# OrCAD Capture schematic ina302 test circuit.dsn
size C
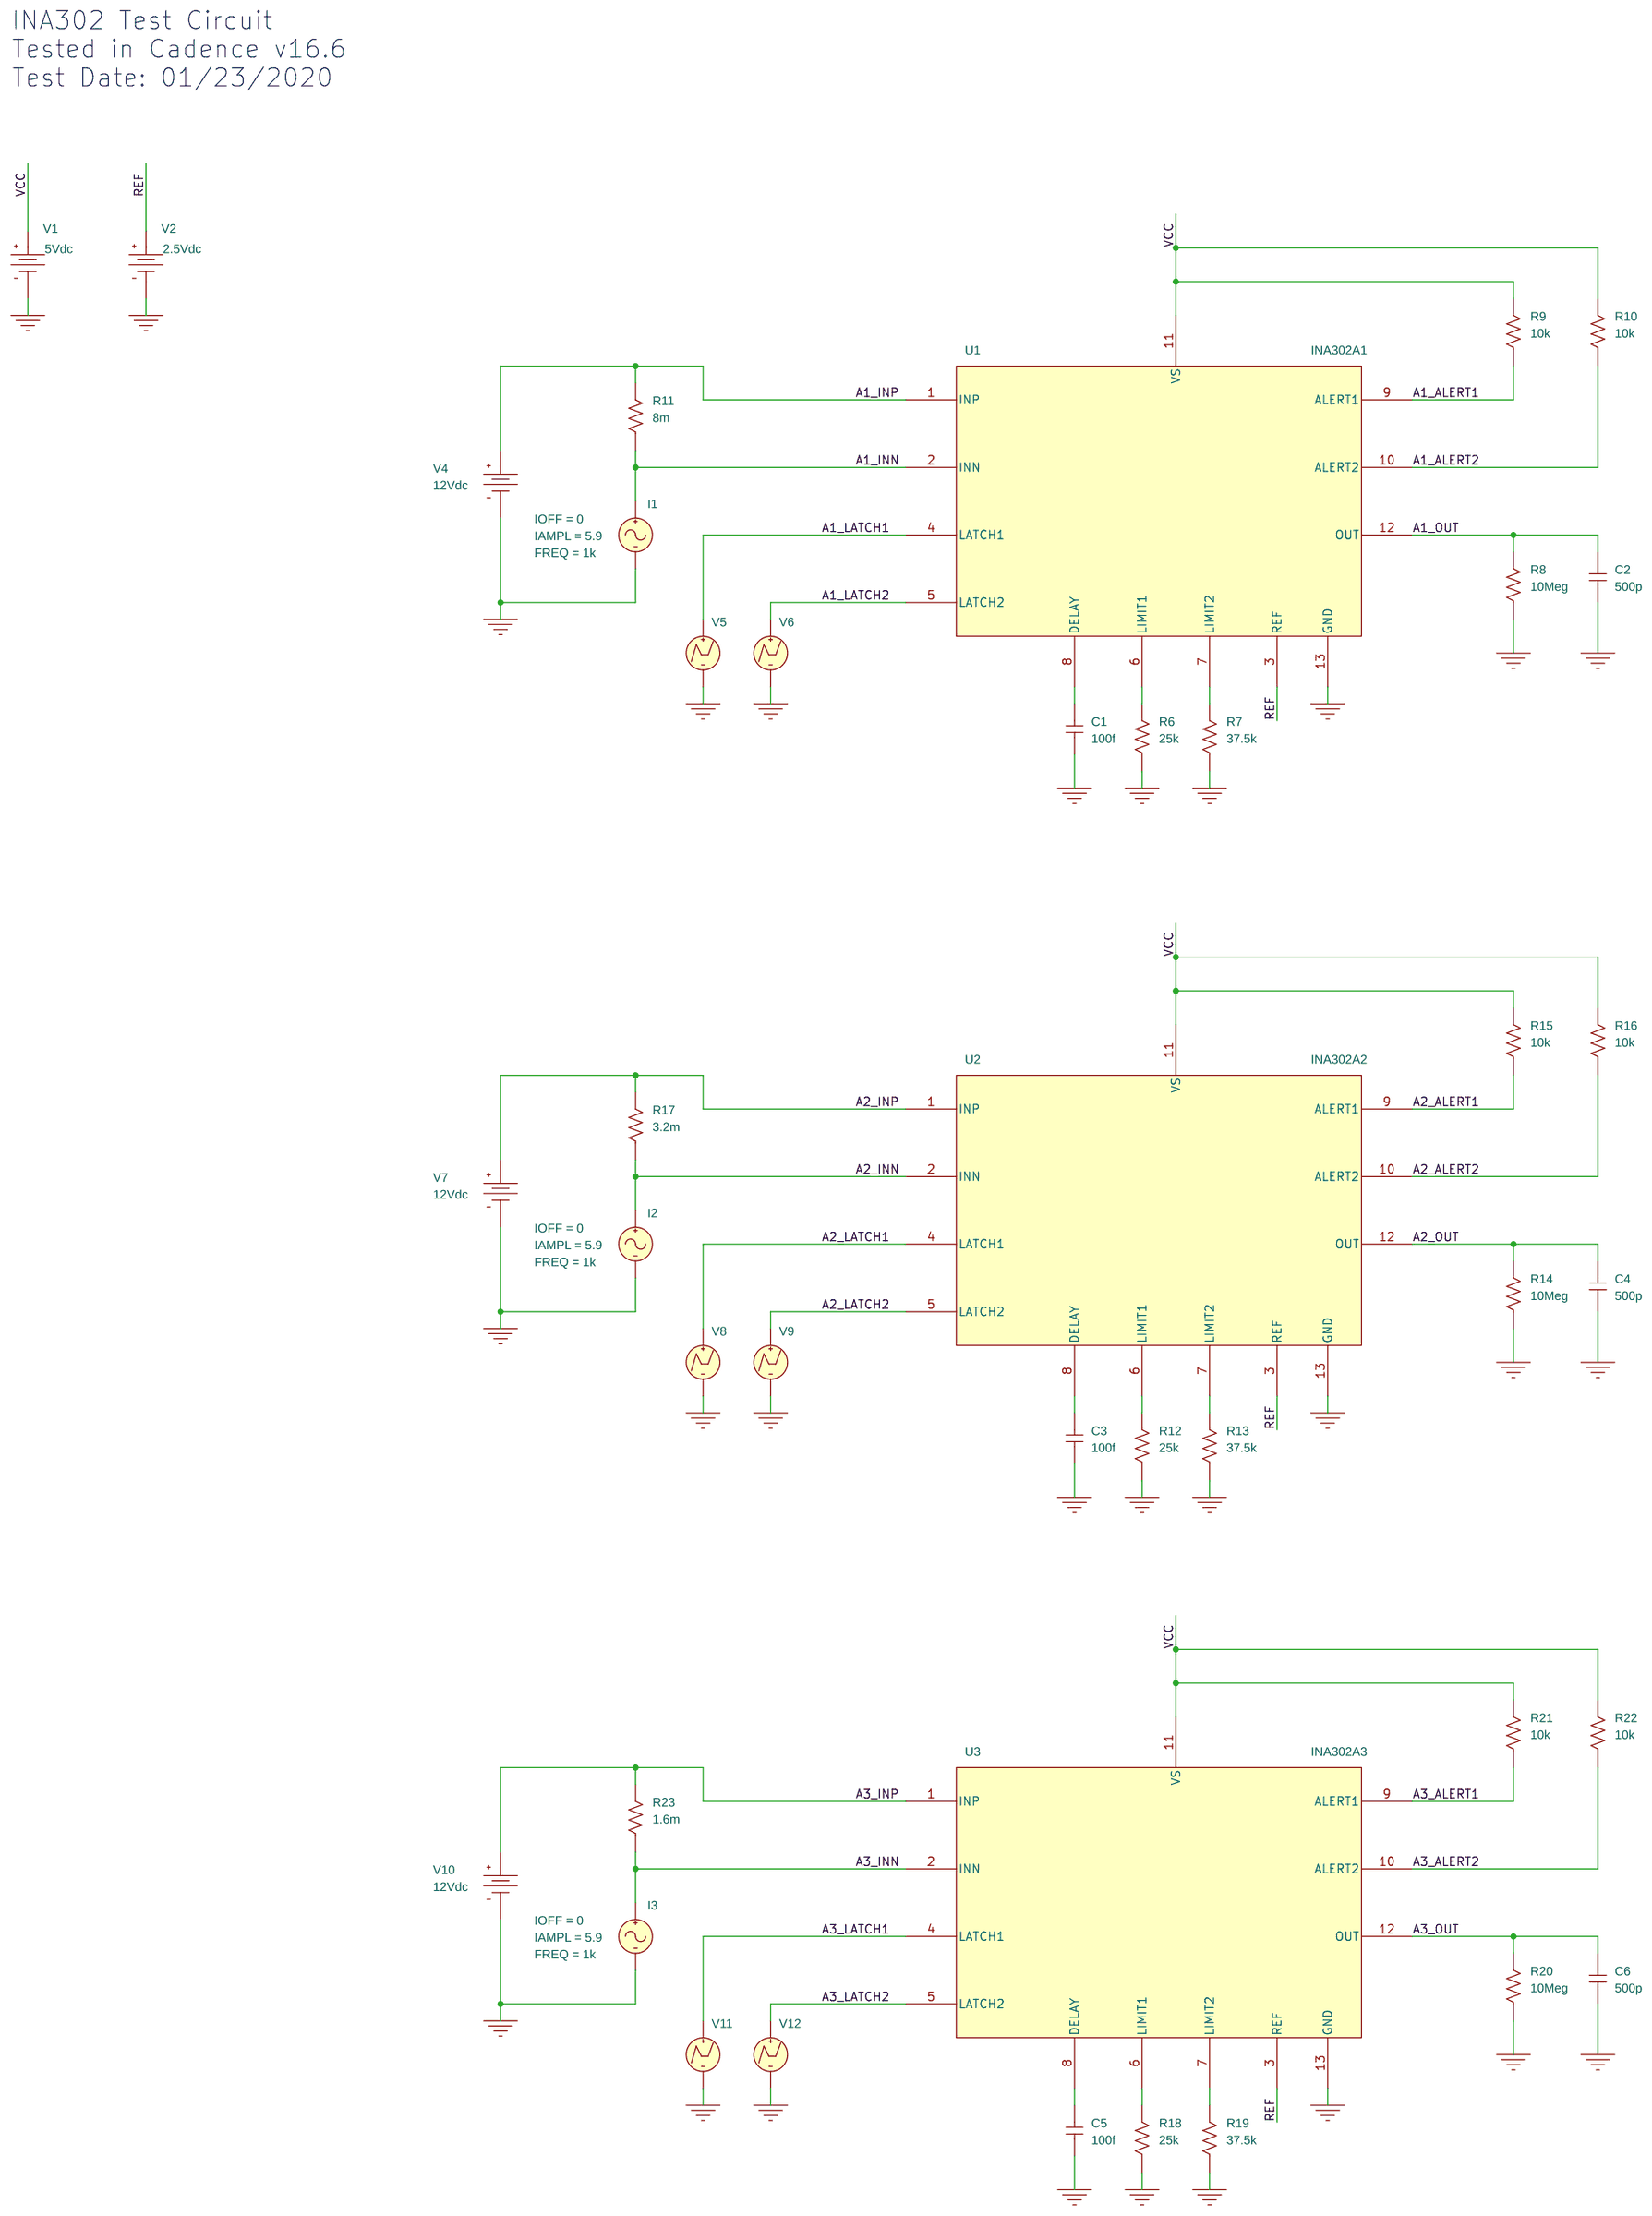
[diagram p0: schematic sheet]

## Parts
C1  100f  [RAD/CK05]
C2  500p  [RAD/CK05]
C3  100f  [RAD/CK05]
C4  500p  [RAD/CK05]
C5  100f  [RAD/CK05]
C6  500p  [RAD/CK05]
I1  ISIN
I2  ISIN
I3  ISIN
R6  25k  [AX/RC05]
R7  37.5k  [AX/RC05]
R8  10Meg  [AX/RC05]
R9  10k  [AX/RC05]
R10  10k  [AX/RC05]
R11  8m  [AX/RC05]
R12  25k  [AX/RC05]
R13  37.5k  [AX/RC05]
R14  10Meg  [AX/RC05]
R15  10k  [AX/RC05]
R16  10k  [AX/RC05]
R17  3.2m  [AX/RC05]
R18  25k  [AX/RC05]
R19  37.5k  [AX/RC05]
R20  10Meg  [AX/RC05]
R21  10k  [AX/RC05]
R22  10k  [AX/RC05]
R23  1.6m  [AX/RC05]
U1  INA302A1
U2  INA302A2
U3  INA302A3
V1  VDC
V2  VDC
V4  VDC
V5  VPWL
V6  VPWL
V7  VDC
V8  VPWL
V9  VPWL
V10  VDC
V11  VPWL
V12  VPWL

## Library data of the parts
C1-C6 = C
I1-I3 = ISIN: FREQ: 1k; IAMPL: 5.9; IOFF: 0
R6-R23 = R
U1 = INA302A1
U2 = INA302A2
U3 = INA302A3
V1 = VDC: DC: 5Vdc
V2 = VDC: DC: 2.5Vdc
V4 V7 V10 = VDC: DC: 12Vdc
V5 V8 V11 = VPWL: T1: 0; T2: 5m; T3: 5.000001m; T4: 9.5m; T5: 9.500001m; V1: 0; V2: 0; V3: 5; V4: 5; V5: 0
V6 V9 V12 = VPWL: T1: 0; T2: 13m; T3: 13.000001m; T4: 18.5m; T5: 18.500001m; V1: 0; V2: 0; V3: 5; V4: 5; V5: 0

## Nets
VCC: R9.2 R10.2 R15.2 R16.2 R21.2 R22.2 U1.11(VS) U2.11(VS) U3.11(VS) V1.0(+)
0: C1.1 C2.1 C3.1 C4.1 C5.1 C6.1 I1.2(-) I2.2(-) I3.2(-) R6.1 R7.1 R8.1 R12.1 R13.1 R14.1 R18.1 R19.1 R20.1 U1.13(GND) U2.13(GND) U3.13(GND) V1.1(-) V2.1(-) V4.1(-) V5.2(-) V6.2(-) V7.1(-) V8.2(-) V9.2(-) V10.1(-) V11.2(-) V12.2(-)
A1_ALERT1: R9.1 U1.9(ALERT1)
A1_ALERT2: R10.1 U1.10(ALERT2)
A1_INN: I1.1(+) R11.1 U1.2(INN)
A1_INP: R11.2 U1.1(INP) V4.0(+)
A1_LATCH1: U1.4(LATCH1) V5.1(+)
A1_LATCH2: U1.5(LATCH2) V6.1(+)
A1_OUT: C2.2 R8.2 U1.12(OUT)
A2_ALERT1: R15.1 U2.9(ALERT1)
A2_ALERT2: R16.1 U2.10(ALERT2)
A2_INN: I2.1(+) R17.1 U2.2(INN)
A2_INP: R17.2 U2.1(INP) V7.0(+)
A2_LATCH1: U2.4(LATCH1) V8.1(+)
A2_LATCH2: U2.5(LATCH2) V9.1(+)
A2_OUT: C4.2 R14.2 U2.12(OUT)
A3_ALERT1: R21.1 U3.9(ALERT1)
A3_ALERT2: R22.1 U3.10(ALERT2)
A3_INN: I3.1(+) R23.1 U3.2(INN)
A3_INP: R23.2 U3.1(INP) V10.0(+)
A3_LATCH1: U3.4(LATCH1) V11.1(+)
A3_LATCH2: U3.5(LATCH2) V12.1(+)
A3_OUT: C6.2 R20.2 U3.12(OUT)
REF: U1.3(REF) U2.3(REF) U3.3(REF) V2.0(+)
N04743: C1.2 U1.8(DELAY)
N04903: R6.2 U1.6(LIMIT1)
N04907: R7.2 U1.7(LIMIT2)
N09009: C3.2 U2.8(DELAY)
N09107: R12.2 U2.6(LIMIT1)
N09113: R13.2 U2.7(LIMIT2)
N10516: C5.2 U3.8(DELAY)
N10614: R18.2 U3.6(LIMIT1)
N10620: R19.2 U3.7(LIMIT2)

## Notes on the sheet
- INA302 Test Circuit
  Tested in Cadence v16.6
  Test Date: 01/23/2020
